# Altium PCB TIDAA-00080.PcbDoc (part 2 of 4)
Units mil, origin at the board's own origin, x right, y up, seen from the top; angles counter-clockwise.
Board outline 7874.02 x 2559.06 mil, 4 copper layers (Top Layer, MidLayer1, MidLayer2, Bottom Layer), stack 61.2 mil thick; 363 components, 169 nets, 940 pads, 199 vias.
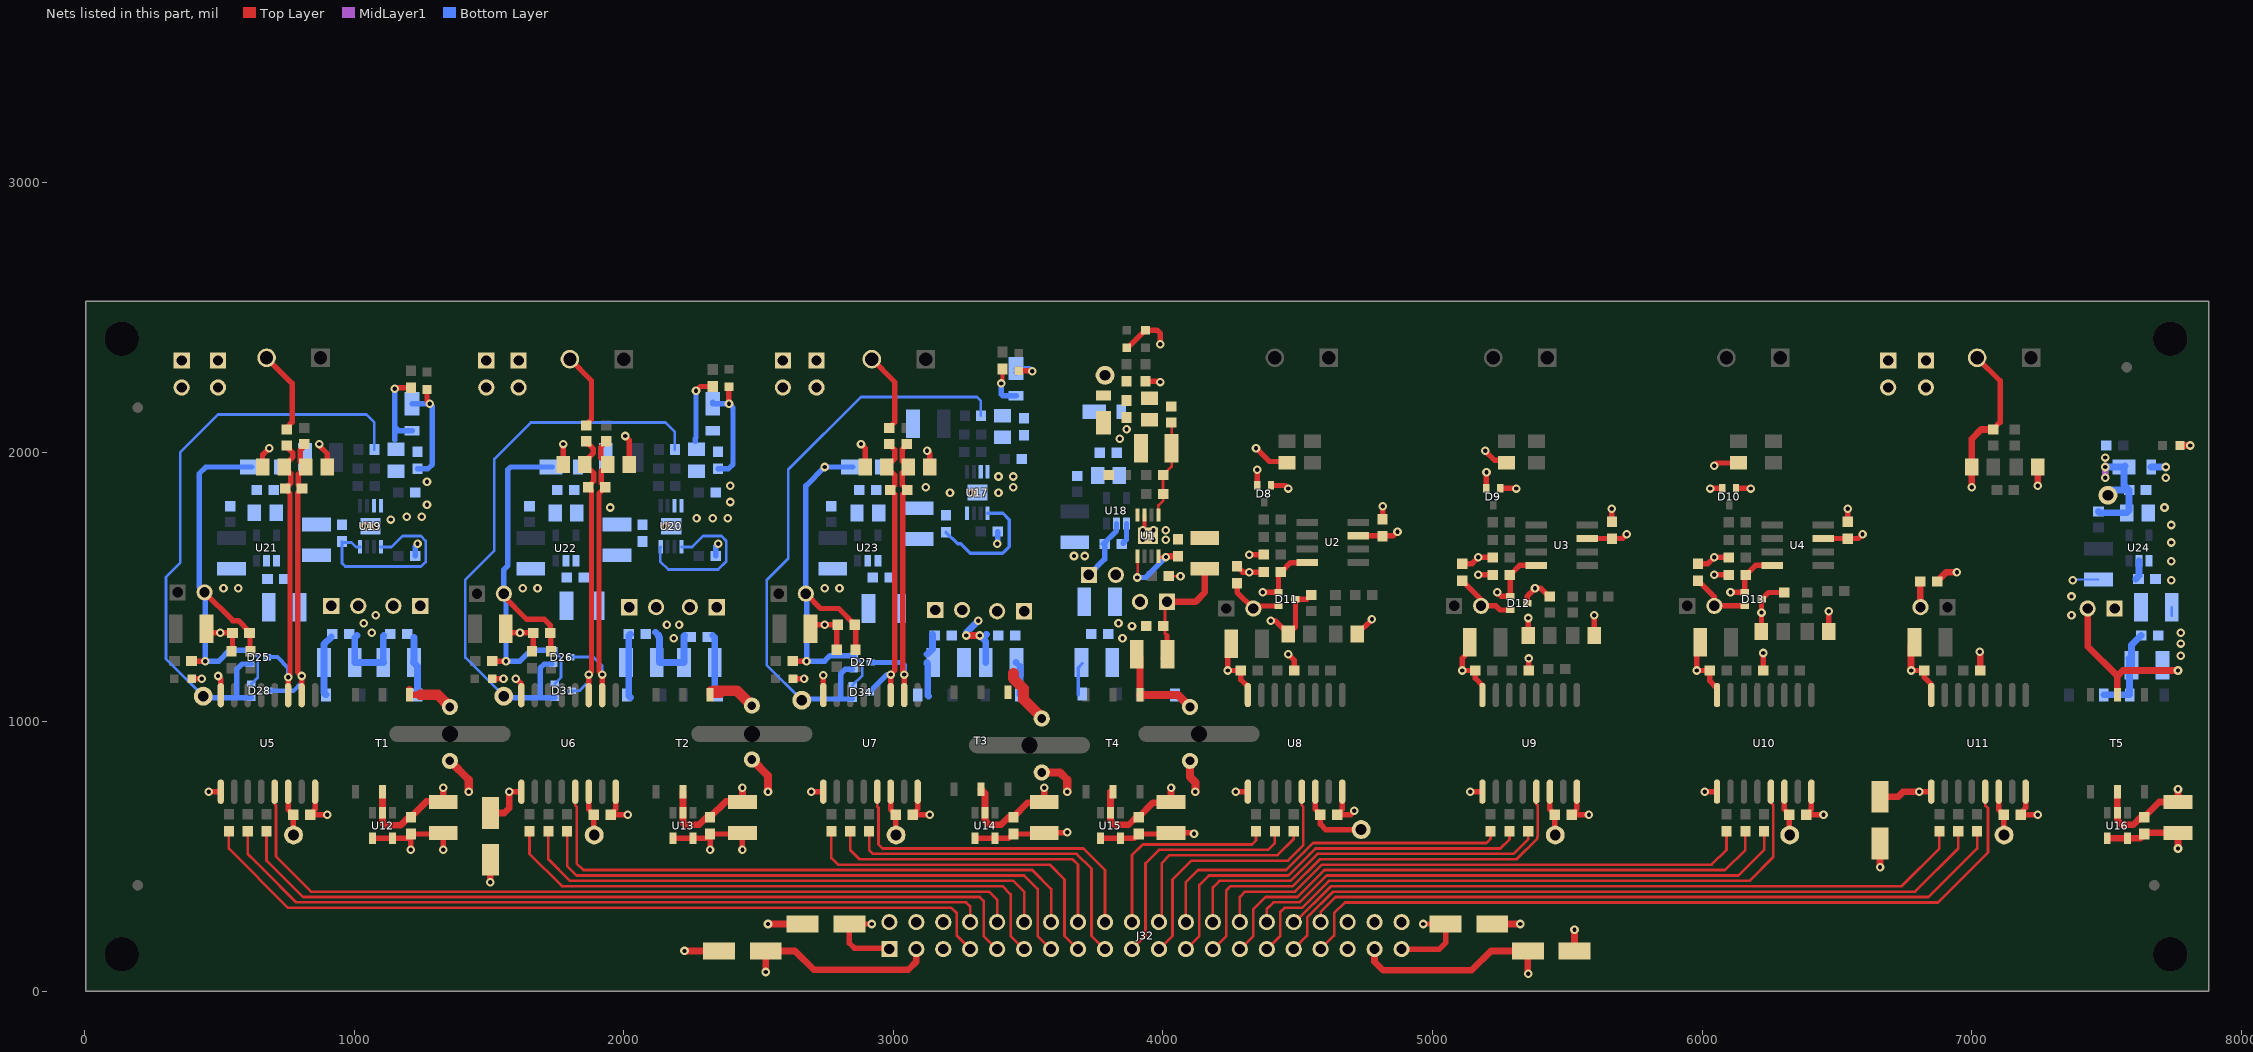
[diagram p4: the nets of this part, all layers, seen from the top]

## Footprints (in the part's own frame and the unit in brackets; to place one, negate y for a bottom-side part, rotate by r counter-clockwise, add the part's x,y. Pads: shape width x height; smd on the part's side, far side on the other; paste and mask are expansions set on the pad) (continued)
TI_Stacked_SolderMask_Small [mil]
  rect 0x0 smd paste-125 mask-125: 0(0,0)
  Top Layer region: 519 vertices and 0 holes, not listed, extent -418.39,-77.79 -237.37,98.14
  Top Layer region: 537 vertices and 1 holes, not listed, extent -104.32,-10.18 14.18,47.26
  Top Layer region: 271 vertices and 0 holes, not listed, extent 124.68,-98.14 197.38,-39.98
  Top Layer region: 193 vertices and 1 holes, not listed, extent 3.27,-98.14 65.79,-39.98
  Top Layer region: 243 vertices and 0 holes, not listed, extent -158.85,-98.14 -100.69,-39.98
  Top Layer region: 249 vertices and 0 holes, not listed, extent 255.54,-98.14 313.7,-39.98
  Top Layer region: -145.76,62.52 -145.04,62.52 -145.04,60.34 -144.31,60.34 -144.31,58.16 -143.58,58.16 -143.58,55.98 -142.86,55.98 -142.86,53.8 -142.13,53.8 -142.13,51.62 -141.4,51.62 -141.4,50.89 -142.13,50.89 -142.13,50.16 -143.58,50.16 -143.58,51.62 -144.31,51.62 -144.31,52.34 -145.04,52.34 -145.04,53.07 -145.76,53.07 -145.76,53.8 -147.22,53.8 -147.22,54.53 -147.94,54.53 -147.94,55.25 -150.13,55.25 -150.13,55.98 -153.03,55.98 -153.03,56.71 -168.3,56.71 -168.3,55.98 -169.03,55.98 -169.03,54.53 -169.75,54.53 -169.75,-2.91 -169.03,-2.91 -169.03,-5.09 -168.3,-5.09 -168.3,-5.82 -167.57,-5.82 -167.57,-6.54 -166.85,-6.54 -166.85,-7.27 -165.39,-7.27 -165.39,-8 -163.94,-8 -163.94,-10.18 -188.66,-10.18 -188.66,-8 -187.2,-8 -187.2,-7.27 -185.75,-7.27 -185.75,-6.54 -185.02,-6.54 -185.02,-5.82 -184.29,-5.82 -184.29,-5.09 -183.57,-5.09 -183.57,-2.18 -182.84,-2.18 -182.84,53.8 -183.57,53.8 -183.57,55.98 -185.02,55.98 -185.02,56.71 -199.56,56.71 -199.56,55.98 -202.47,55.98 -202.47,55.25 -204.65,55.25 -204.65,54.53 -205.38,54.53 -205.38,53.8 -206.83,53.8 -206.83,53.07 -207.56,53.07 -207.56,52.34 -208.29,52.34 -208.29,51.62 -209.01,51.62 -209.01,50.89 -209.74,50.89 -209.74,50.16 -210.47,50.16 -210.47,50.89 -211.19,50.89 -211.19,53.07 -210.47,53.07 -210.47,54.53 -209.74,54.53 -209.74,56.71 -209.01,56.71 -209.01,58.89 -208.29,58.89 -208.29,61.07 -207.56,61.07 -207.56,63.25 -206.83,63.25 -206.83,64.7 -145.76,64.7
  Top Layer region: 246.82,-41.44 247.54,-41.44 247.54,-42.89 248.27,-42.89 248.27,-45.07 249,-45.07 249,-47.26 249.72,-47.26 249.72,-48.71 250.45,-48.71 250.45,-50.89 251.18,-50.89 251.18,-53.07 250.45,-53.07 250.45,-53.8 249.72,-53.8 249.72,-53.07 249,-53.07 249,-52.34 248.27,-52.34 248.27,-51.62 246.82,-51.62 246.82,-50.89 246.09,-50.89 246.09,-50.16 245.36,-50.16 245.36,-49.44 244.64,-49.44 244.64,-48.71 243.18,-48.71 243.18,-47.98 241,-47.98 241,-47.26 238.09,-47.26 238.09,-46.53 222.83,-46.53 222.83,-47.26 220.64,-47.26 220.64,-48.71 219.92,-48.71 219.92,-63.98 237.37,-63.98 237.37,-63.25 239.55,-63.25 239.55,-62.52 240.27,-62.52 240.27,-61.8 241,-61.8 241,-60.34 241.73,-60.34 241.73,-58.89 243.91,-58.89 243.91,-74.88 241.73,-74.88 241.73,-73.43 241,-73.43 241,-71.97 240.27,-71.97 240.27,-71.25 238.09,-71.25 238.09,-70.52 219.92,-70.52 219.92,-88.69 220.64,-88.69 220.64,-90.15 241.73,-90.15 241.73,-89.42 244.64,-89.42 244.64,-88.69 246.09,-88.69 246.09,-87.97 247.54,-87.97 247.54,-87.24 248.27,-87.24 248.27,-86.51 249,-86.51 249,-85.79 249.72,-85.79 249.72,-85.06 250.45,-85.06 250.45,-84.33 251.18,-84.33 251.18,-83.61 251.91,-83.61 251.91,-82.88 253.36,-82.88 253.36,-83.61 254.09,-83.61 254.09,-85.06 253.36,-85.06 253.36,-86.51 252.63,-86.51 252.63,-88.69 251.91,-88.69 251.91,-90.15 251.18,-90.15 251.18,-92.33 250.45,-92.33 250.45,-93.78 249.72,-93.78 249.72,-95.96 249,-95.96 249,-97.42 201.74,-97.42 201.74,-95.24 203.2,-95.24 203.2,-94.51 204.65,-94.51 204.65,-93.78 206.1,-93.78 206.1,-93.06 206.83,-93.06 206.83,-90.88 207.56,-90.88 207.56,-45.8 206.83,-45.8 206.83,-44.35 206.1,-44.35 206.1,-43.62 205.38,-43.62 205.38,-42.89 203.92,-42.89 203.92,-42.17 201.74,-42.17 201.74,-39.98 246.82,-39.98
  Top Layer region: -110.14,45.8 -109.41,45.8 -109.41,44.35 -108.69,44.35 -108.69,42.17 -107.96,42.17 -107.96,39.98 -107.23,39.98 -107.23,37.8 -106.51,37.8 -106.51,36.35 -105.78,36.35 -105.78,33.44 -107.96,33.44 -107.96,34.17 -108.69,34.17 -108.69,34.9 -109.41,34.9 -109.41,35.62 -110.14,35.62 -110.14,36.35 -110.87,36.35 -110.87,37.08 -111.59,37.08 -111.59,37.8 -113.05,37.8 -113.05,38.53 -114.5,38.53 -114.5,39.26 -116.68,39.26 -116.68,39.98 -135.59,39.98 -135.59,39.26 -136.31,39.26 -136.31,38.53 -137.04,38.53 -137.04,23.26 -118.14,23.26 -118.14,23.99 -116.68,23.99 -116.68,24.72 -115.96,24.72 -115.96,26.17 -115.23,26.17 -115.23,27.63 -113.05,27.63 -113.05,11.63 -115.23,11.63 -115.23,13.81 -115.96,13.81 -115.96,14.54 -116.68,14.54 -116.68,15.27 -117.41,15.27 -117.41,15.99 -119.59,15.99 -119.59,16.72 -137.04,16.72 -137.04,-1.45 -136.31,-1.45 -136.31,-2.91 -134.13,-2.91 -134.13,-3.63 -118.86,-3.63 -118.86,-2.91 -113.78,-2.91 -113.78,-2.18 -111.59,-2.18 -111.59,-1.45 -110.14,-1.45 -110.14,-0.73 -109.41,-0.73 -109.41,0 -107.96,0 -107.96,0.73 -107.23,0.73 -107.23,1.45 -106.51,1.45 -106.51,2.18 -105.78,2.18 -105.78,2.91 -105.05,2.91 -105.05,3.63 -104.32,3.63 -104.32,4.36 -103.6,4.36 -103.6,3.63 -102.87,3.63 -102.87,2.18 -103.6,2.18 -103.6,0 -104.32,0 -104.32,-1.45 -105.05,-1.45 -105.05,-3.63 -105.78,-3.63 -105.78,-5.09 -106.51,-5.09 -106.51,-7.27 -107.23,-7.27 -107.23,-8.72 -107.96,-8.72 -107.96,-10.18 -155.21,-10.18 -155.21,-8 -153.03,-8 -153.03,-7.27 -151.58,-7.27 -151.58,-6.54 -150.85,-6.54 -150.85,-5.82 -150.13,-5.82 -150.13,-4.36 -149.4,-4.36 -149.4,41.44 -150.13,41.44 -150.13,42.89 -150.85,42.89 -150.85,43.62 -151.58,43.62 -151.58,44.35 -153.76,44.35 -153.76,45.07 -155.21,45.07 -155.21,47.26 -110.14,47.26
  Top Layer region: 293 vertices and 0 holes, not listed, extent 12,-10.9 59.25,47.98
  Top Layer region: 295 vertices and 0 holes, not listed, extent -98.51,-98.14 -51.25,-39.26
  Top Layer region: 283 vertices and 0 holes, not listed, extent 371.13,-98.14 418.39,-39.26
  Top Layer region: 121.05,-42.17 118.86,-42.17 118.86,-42.89 118.14,-42.89 118.14,-43.62 117.41,-43.62 117.41,-44.35 116.68,-44.35 116.68,-45.8 115.96,-45.8 115.96,-82.15 115.23,-82.15 115.23,-85.79 114.5,-85.79 114.5,-87.24 113.78,-87.24 113.78,-88.69 113.05,-88.69 113.05,-90.15 112.32,-90.15 112.32,-90.88 111.59,-90.88 111.59,-92.33 110.87,-92.33 110.87,-93.06 110.14,-93.06 110.14,-93.78 108.69,-93.78 108.69,-94.51 107.96,-94.51 107.96,-95.24 106.51,-95.24 106.51,-95.96 104.32,-95.96 104.32,-96.69 102.14,-96.69 102.14,-97.42 97.78,-97.42 97.78,-98.14 86.15,-98.14 86.15,-97.42 81.79,-97.42 81.79,-96.69 79.61,-96.69 79.61,-95.96 77.43,-95.96 77.43,-95.24 75.97,-95.24 75.97,-94.51 74.52,-94.51 74.52,-93.78 73.79,-93.78 73.79,-93.06 72.34,-93.06 72.34,-92.33 71.61,-92.33 71.61,-91.6 70.88,-91.6 70.88,-90.88 70.16,-90.88 70.16,-90.15 69.43,-90.15 69.43,-88.69 68.7,-88.69 68.7,-87.97 67.97,-87.97 67.97,-86.51 67.25,-86.51 67.25,-84.33 66.52,-84.33 66.52,-47.26 65.79,-47.26 65.79,-45.07 65.07,-45.07 65.07,-43.62 64.34,-43.62 64.34,-42.89 62.89,-42.89 62.89,-42.17 60.7,-42.17 60.7,-39.98 83.97,-39.98 83.97,-42.17 81.79,-42.17 81.79,-42.89 80.33,-42.89 80.33,-43.62 79.61,-43.62 79.61,-45.07 78.88,-45.07 78.88,-47.98 78.15,-47.98 78.15,-79.24 78.88,-79.24 78.88,-82.88 79.61,-82.88 79.61,-85.06 80.33,-85.06 80.33,-86.51 81.06,-86.51 81.06,-87.24 81.79,-87.24 81.79,-87.97 82.51,-87.97 82.51,-88.69 83.97,-88.69 83.97,-89.42 85.42,-89.42 85.42,-90.15 88.33,-90.15 88.33,-90.88 98.51,-90.88 98.51,-90.15 101.42,-90.15 101.42,-89.42 102.87,-89.42 102.87,-88.69 103.6,-88.69 103.6,-87.97 104.32,-87.97 104.32,-87.24 105.05,-87.24 105.05,-86.51 105.78,-86.51 105.78,-85.79 106.51,-85.79 106.51,-83.61 107.23,-83.61 107.23,-80.7 107.96,-80.7 107.96,-47.26 107.23,-47.26 107.23,-45.07 106.51,-45.07 106.51,-43.62 105.78,-43.62 105.78,-42.89 104.32,-42.89 104.32,-42.17 102.14,-42.17 102.14,-39.98 121.05,-39.98
  Top Layer region: -289.71,63.25 -290.44,63.25 -290.44,59.61 -291.16,59.61 -291.16,55.98 -291.89,55.98 -291.89,52.34 -292.62,52.34 -292.62,48.71 -293.34,48.71 -293.34,45.07 -294.07,45.07 -294.07,41.44 -294.8,41.44 -294.8,37.8 -295.53,37.8 -295.53,34.17 -296.25,34.17 -296.25,30.53 -296.98,30.53 -296.98,26.9 -297.71,26.9 -297.71,23.26 -298.43,23.26 -298.43,19.63 -299.16,19.63 -299.16,15.99 -299.89,15.99 -299.89,12.36 -300.61,12.36 -300.61,8.72 -301.34,8.72 -301.34,5.09 -302.07,5.09 -302.07,1.45 -302.8,1.45 -302.8,-2.18 -303.52,-2.18 -303.52,-5.82 -304.25,-5.82 -304.25,-9.45 -321.7,-9.45 -321.7,-7.27 -320.97,-7.27 -320.97,-3.63 -320.24,-3.63 -320.24,0 -319.52,0 -319.52,3.63 -318.79,3.63 -318.79,7.27 -318.06,7.27 -318.06,10.9 -317.34,10.9 -317.34,14.54 -316.61,14.54 -316.61,18.17 -315.88,18.17 -315.88,21.81 -315.15,21.81 -315.15,25.44 -314.43,25.44 -314.43,29.08 -313.7,29.08 -313.7,32.71 -312.97,32.71 -312.97,36.35 -312.25,36.35 -312.25,39.98 -311.52,39.98 -311.52,43.62 -310.79,43.62 -310.79,47.26 -310.07,47.26 -310.07,50.89 -309.34,50.89 -309.34,54.53 -308.61,54.53 -308.61,58.16 -307.88,58.16 -307.88,61.8 -307.16,61.8 -307.16,64.7 -289.71,64.7
  Top Layer region: -1.82,-42.17 -1.09,-42.17 -1.09,-45.07 -0.36,-45.07 -0.36,-47.26 0.36,-47.26 0.36,-49.44 1.09,-49.44 1.09,-51.62 1.82,-51.62 1.82,-55.25 0.36,-55.25 0.36,-54.53 -0.36,-54.53 -0.36,-53.8 -1.09,-53.8 -1.09,-53.07 -1.82,-53.07 -1.82,-52.34 -2.54,-52.34 -2.54,-51.62 -3.27,-51.62 -3.27,-50.89 -4,-50.89 -4,-50.16 -4.73,-50.16 -4.73,-49.44 -5.45,-49.44 -5.45,-48.71 -6.18,-48.71 -6.18,-47.98 -8.36,-47.98 -8.36,-47.26 -11.27,-47.26 -11.27,-46.53 -17.81,-46.53 -17.81,-47.26 -18.54,-47.26 -18.54,-47.98 -19.27,-47.98 -19.27,-90.88 -18.54,-90.88 -18.54,-93.06 -17.81,-93.06 -17.81,-93.78 -16.36,-93.78 -16.36,-94.51 -14.18,-94.51 -14.18,-95.24 -12.72,-95.24 -12.72,-97.42 -37.44,-97.42 -37.44,-95.24 -36.71,-95.24 -36.71,-94.51 -34.53,-94.51 -34.53,-93.78 -33.08,-93.78 -33.08,-93.06 -32.35,-93.06 -32.35,-91.6 -31.62,-91.6 -31.62,-47.26 -33.08,-47.26 -33.08,-46.53 -39.62,-46.53 -39.62,-47.26 -42.53,-47.26 -42.53,-47.98 -43.98,-47.98 -43.98,-48.71 -44.71,-48.71 -44.71,-49.44 -46.16,-49.44 -46.16,-50.16 -46.89,-50.16 -46.89,-50.89 -47.62,-50.89 -47.62,-52.34 -48.35,-52.34 -48.35,-53.07 -49.07,-53.07 -49.07,-53.8 -49.8,-53.8 -49.8,-54.53 -50.53,-54.53 -50.53,-55.25 -51.98,-55.25 -51.98,-54.53 -52.71,-54.53 -52.71,-53.8 -51.98,-53.8 -51.98,-51.62 -51.25,-51.62 -51.25,-49.44 -50.53,-49.44 -50.53,-47.26 -49.8,-47.26 -49.8,-44.35 -49.07,-44.35 -49.07,-42.17 -48.35,-42.17 -48.35,-39.98 -1.82,-39.98
  Top Layer region: -163.21,-23.99 -163.94,-23.99 -163.94,-24.72 -166.12,-24.72 -166.12,-25.44 -167.57,-25.44 -167.57,-26.17 -168.3,-26.17 -168.3,-26.9 -169.03,-26.9 -169.03,-29.08 -169.75,-29.08 -169.75,-90.15 -169.03,-90.15 -169.03,-92.33 -168.3,-92.33 -168.3,-93.06 -167.57,-93.06 -167.57,-93.78 -166.12,-93.78 -166.12,-94.51 -163.94,-94.51 -163.94,-95.24 -163.21,-95.24 -163.21,-97.42 -189.38,-97.42 -189.38,-95.24 -188.66,-95.24 -188.66,-94.51 -186.48,-94.51 -186.48,-93.78 -185.02,-93.78 -185.02,-93.06 -184.29,-93.06 -184.29,-91.6 -183.57,-91.6 -183.57,-89.42 -182.84,-89.42 -182.84,-29.81 -183.57,-29.81 -183.57,-27.63 -184.29,-27.63 -184.29,-26.17 -185.75,-26.17 -185.75,-25.44 -186.48,-25.44 -186.48,-24.72 -188.66,-24.72 -188.66,-23.99 -189.38,-23.99 -189.38,-22.54 -163.21,-22.54
  Top Layer region: 364.59,-40.71 365.32,-40.71 365.32,-42.89 366.04,-42.89 366.04,-45.07 366.77,-45.07 366.77,-47.26 367.5,-47.26 367.5,-50.16 368.23,-50.16 368.23,-52.34 368.95,-52.34 368.95,-55.25 366.77,-55.25 366.77,-53.8 366.04,-53.8 366.04,-53.07 365.32,-53.07 365.32,-52.34 364.59,-52.34 364.59,-51.62 363.86,-51.62 363.86,-50.89 363.14,-50.89 363.14,-50.16 362.41,-50.16 362.41,-49.44 361.68,-49.44 361.68,-48.71 360.96,-48.71 360.96,-47.98 358.77,-47.98 358.77,-47.26 355.87,-47.26 355.87,-46.53 349.32,-46.53 349.32,-47.26 348.6,-47.26 348.6,-47.98 347.87,-47.98 347.87,-91.6 348.6,-91.6 348.6,-93.06 349.32,-93.06 349.32,-93.78 350.78,-93.78 350.78,-94.51 352.96,-94.51 352.96,-95.24 353.69,-95.24 353.69,-97.42 329.69,-97.42 329.69,-95.24 330.42,-95.24 330.42,-94.51 332.6,-94.51 332.6,-93.78 334.06,-93.78 334.06,-93.06 334.78,-93.06 334.78,-91.6 335.51,-91.6 335.51,-47.98 334.78,-47.98 334.78,-47.26 334.06,-47.26 334.06,-46.53 327.51,-46.53 327.51,-47.26 324.61,-47.26 324.61,-47.98 323.15,-47.98 323.15,-48.71 321.7,-48.71 321.7,-49.44 320.97,-49.44 320.97,-50.16 320.24,-50.16 320.24,-50.89 319.52,-50.89 319.52,-51.62 318.79,-51.62 318.79,-53.07 318.06,-53.07 318.06,-53.8 317.34,-53.8 317.34,-54.53 316.61,-54.53 316.61,-55.25 315.15,-55.25 315.15,-54.53 314.43,-54.53 314.43,-53.8 315.15,-53.8 315.15,-51.62 315.88,-51.62 315.88,-48.71 316.61,-48.71 316.61,-46.53 317.34,-46.53 317.34,-44.35 318.06,-44.35 318.06,-42.17 318.79,-42.17 318.79,-39.98 364.59,-39.98
  Top Layer region: -285.35,85.79 -286.07,85.79 -286.07,82.15 -286.8,82.15 -286.8,78.52 -287.53,78.52 -287.53,74.88 -288.26,74.88 -288.26,71.97 -305.7,71.97 -305.7,73.43 -304.98,73.43 -304.98,77.06 -304.25,77.06 -304.25,80.7 -303.52,80.7 -303.52,84.33 -302.8,84.33 -302.8,87.97 -302.07,87.97 -302.07,88.69 -285.35,88.69
TP-040_RND [mil]
  round 70 / inner round 62 / far side round 62 hole 40: 1(0,0)
  silkscreen extent -45,-45 45,45

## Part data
C1 C85 C90 C92 C95 C102 C103 C104 C106: library part C2012X5R1H475K125AB, "CAP, CERM, 4.7uF, 50V, +/-10%, X5R, 0805"
C2 C20 C22 C24 C26 C29 C30 C31 C32 C33 C34 C35 C36 C39 C42 C45 C46 C47 C48 C50 C52 C54 C56 C69 C71 C73 C75 C77 C86 C87 C89 C93 C96 C98 C100 C101 C105 C112 C114 C115 C118 C119 C122 C124 C127 C128 C130 C132 C133 C134 C135 C137: library part C0603C104K5RACTU, "CAP, CERM, 0.1uF, 50V, +/-10%, X7R, 0603"
C3 C4 C5 C6 C7 C8 C10 C11 C37 C38 C40 C41 C43 C44: "CAP, CERM, 47pF, 500V, +/-5%, C0G/NP0, 0805"
C9 C17 C18 C19 C28 C49 C70 C72 C74 C76 C78 C84 C88 C91 C107 C108 C109 C111 C113 C117 C121 C123 C125 C126 C129 C131 C136 C138 C139 C140 C141 C142 C143 C144 C145 C146 C147 C148 C149: library part GMK325AB7106MM-T, "CAP, CERM, 10uF, 35V, +/-20%, X7R, 1210"
C12 C13 C14 C16 C51 C53 C55: "CAP, CERM, 1500pF, 100V, +/-10%, X7R, 0603"
C15 C27 C94 C97 C99 C110 C116 C120: library part 06031C103JAT2A, "CAP, CERM, 0.01uF, 100V, +/-5%, X7R, 0603"
C21 C23 C25: library part 06031C472KAT2A, "CAP, CERM, 4700pF, 100V, +/-10%, X7R, 0603"
C57 C58 C59 C60: library part 202R18W102KV4E, "CAP CER 1000PF 1KV 10% RADIAL"
C61 C62 C63 C64 C65 C66 C67: library part 06033C104JAT2A, "CAP, CERM, 0.1uF, 25V, +/-5%, X7R, 0603"
C68 C79 C80 C81 C82 C83: "CAP, AL, 22uF, 25V, +/-20%, 0.76 ohm, SMD"
D1 D2 D3 D4 D5 D7 D14 D15 D16: library part "LED_LG L29K-G2J1-24-Z", "LED SmartLED Green 570NM"
D6 D17 D18 D19 D20 D21 D22 D23 D24: library part DFLZ6V2-7, "Diode, Zener, 6.2V, 1W, PowerDI123"
D8 D9 D10 D11 D12 D13 D25 D26 D27 D28 D31 D34: library part BAV99WT1G, "Diode, P-N, 70V, 0.2A, SOT-323"
D29 D30 D32 D33 D35 D36 D37 D38 D39 D40: library part MBR0520LT1G, "Diode, Schottky, 20V, 0.5A, SOD-123"
FB1 FB8 FB9 FB10 FB11 FB12 FB13 FB14 FB15: library part MMZ1608B102C, "FERRITE CHIP 1000 OHM 300MA 0603"
FB2 FB3 FB4 FB5 FB6 FB7 FB16 FB17 FB18 FB19 FB20 FB21 FB22 FB23: "FERRITE CHIP 1000 OHM 300MA 0603"
FID1 FID2 FID3 FID4 FID5 FID6 FID7 FID8: library part Fiducial, "Fiducial mark.  There is nothing to buy or mount."
J1 J2 J3 J4 J5 J6 J7 J8 J16 J17 J18 J19 J20 J21 J22 J23 J24 J25 J26 J27 J28 J29 J30 J31: library part JUMPER_2X100MIL, "Header, Male 2-pin, 100mil spacing,"
J9 J10 J11 J12 J13 J14 J15: "TERMINAL BLOCK 5.08MM VERT 2POS, TH"
J32: library part CONN_61304021021, "Connector, Right Angle 2x20 pin, 100mil spacing"
LBL1: library part THT-14-423-10, "Thermal Transfer Printable Labels, 0.650\" W x 0.200\" H - 10,000 per roll"
Logo1: library part TI_Logo, "Texas Instrument Corporate Signature"
MH1 MH2 MH3 MH4: library part "NY PMS 440 0025 PH", "Mountin hole, NPTH Drill 3.2mm"
R1 R2 R3 R4 R5 R28 R30 R32 R60: library part CRCW06033K90JNEA, "RES, 3.9k ohm, 5%, 0.1W, 0603"
R6 R9 R12: "RES, 0 ohm, 5%, 0.1W, 0603"
R7 R8 R10 R11 R13 R19: "RES, 0 ohm, 5%, 0.125W, 0805"
R14 R63 R64 R65: library part CRCW060311K5FKEA, "RES, 11.5k ohm, 1%, 0.1W, 0603"
R15 R59 R61 R62: library part RT0603BRD0737KL, "RES 37.4K OHM 1/10W .1% 0603 SMD"
R16 R17 R18: library part RC0603FR-074K7L, "RES, 4.70k ohm, 1%, 0.1W, 0603"
R21 R24 R27 R29 R31 R33 R34 R35 R36 R37 R40 R43 R45 R49 R52 R54 R57: library part CRCW06030000Z0EA, "RES, 0 ohm, 5%, 0.1W, 0603"
R38 R39 R41 R42 R44 R46 R47 R48 R50 R51 R53 R55 R56 R58: library part CRCW060310R0FKEA, "RES, 10.0 ohm, 1%, 0.1W, 0603"
T1 T2 T3 T4 T5: library part TRNSFMR, "Transformer 469uH SMD"
TP1 TP2 TP3 TP4 TP5 TP6 TP7 TP8 TP9 TP10 TP11 TP12: library part TP-040_RND, "Test Point, O.040 Hole"
U1 U17 U20: library part TPS7A3001DGNR, "-36V, -200mA, Ultralow-Noise, Negative Linear Regulator"
U2 U3 U4: library part OPA211AID, "IC, 1.1nV/vHz Noise, Low Power, Precision OpAmp"
U5 U6 U7 U8 U9 U10 U11: library part AMC1304L25, "20 MHz, Isolated Delta-Sigma Modulator, LVDS interface:"
U12 U13 U14 U15 U16: "Transformer Driver for Isolated Power Supplies, DBV0005A"
U18 U21 U22 U23 U24: "Regulator, LDO, 5V, 0.15A, SOT23-5"
U19: "-36V, -200mA, Ultralow-Noise, Negative Linear Regulator"
ZZ1: library part AssemblyNoteLabel, "This Assembly Note is for PCB labels only"
ZZ2: library part AssemblyNote, "These assemblies are ESD sensitive, ESD precautions shall be observed."
ZZ3: library part AssemblyNote, "These assemblies must be clean and free from flux and all contaminants. Use of no clean flux is not acceptable."
ZZ4: library part AssemblyNote, "These assemblies must comply with workmanship standards IPC-A-610 Class 2, unless otherwise specified."

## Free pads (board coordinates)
  oval 450x60 hole 60 slot 450 at 0 deg unplated mask+10: 0(1355,955) 0(2475,955) 0(3505,913) 0(4133.86,955)

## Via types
v1: diameter 32, hole 16, Top Layer to Bottom Layer, tented both sides, 199 vias

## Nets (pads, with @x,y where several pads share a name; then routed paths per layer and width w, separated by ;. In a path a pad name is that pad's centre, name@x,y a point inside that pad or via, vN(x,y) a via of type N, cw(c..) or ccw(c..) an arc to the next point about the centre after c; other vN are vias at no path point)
+3.3V_DVDD: C61.2 C62.2 C63.2 C64.2 C65.2 C66.2 C67.2 C80.1 C81.1 J32.1 J32.39 TP6.1 TP7.1 TP8.1 TP9.1 TP10.1 TP11.1 TP12.1 U5.14 U6.14 U7.14 U8.14 U9.14 U10.14 U11.14 | length 1942.7
  Top Layer w20: U5.14@755,740.55 755,675 C61.2@775,655 ; C61.2@773.5,655 773.5,586.5 TP6.1@780,580 ; U6.14@1870,740.55 1870,675 C62.2@1890,655 ; C62.2@1888.5,655 1888.5,586.5 TP7.1@1890,585 ; v1(2920,250) C80.1@2836.61,250 2836.61,178.39 2855,160 2981.7,160 J32.1@2985.01,156.69 ; U7.14@2990,740.87 2990,675 C66.2@3010,655 ; C66.2@3008.5,655 3008.5,581.5 TP8.1@3010,580 ; U8.14@4565,740.87 4565,675 C67.2@4585,655 ; C67.2@4583.5,655 4583.5,620 4603.5,600 TP9.1@4735,600 ; J32.39@4885.01,156.69 5025,156.69 5048.39,180.08 C81.1@5048.39,250 v1(4965,250) ; U9.14@5435,740.87 5435,675 C63.2@5455,655 ; C63.2@5453.5,655 5453.5,581.5 TP10.1@5455,580 ; U10.14@6305,740.87 6305,675 C64.2@6325,655 ; C64.2@6323.5,655 6323.5,581.5 TP11.1@6325,580 ; U11.14@7100,740.87 7100,675 C65.2@7120,655 ; C65.2@7118.5,655 7118.5,581.5 TP12.1@7120,580
+5.0V_PH: C22.2 C24.2 C26.2 C36.1 C39.1 C42.1 C87.1 C95.2 D8.2 D9.2 D10.2 D11.2 D12.2 D13.2 D18.1 FB11.2 J28.2 J29.2 J30.2 R2.2 R34.1 R35.1 R36.1 U2.7 U3.7 U4.7 | length 1544
  Top Layer w20: R2.2@3935,2263.5 3988.5,2263.5 3990,2265 v1(3990,2260) ; C36.1@4275,1513.5 4275,1480 J28.2@4335,1420 4344.41,1429.41 D11.2@4428.5,1429.41 ; D8.2@4349.41,1876.5 4349.41,1934.41 v1(4350,1935) ; v1(4465,1250) 4486.5,1228.5 R34.1@4486.5,1190 ; U2.7@4724,1690 4855,1690 v1(4870,1705) ; C39.1@5110,1523.5 5180,1453.5 J29.2@5180,1430 5235,1430 5250.59,1414.41 D12.2@5288.5,1414.41 ; D9.2@5199.41,1866.5 5199.41,1924.41 v1(5200,1925) ; R35.1@5356.5,1190 v1(5356.5,1235) ; U3.7@5574,1680 5705,1680 v1(5720,1695) ; C42.1@5985,1523.5 6045,1463.5 J30.2@6045,1430 6157.91,1430 D13.2@6158.5,1429.41 ; v1(6030,1865) 6031.5,1866.5 D10.2@6074.41,1866.5 ; R36.1@6226.5,1190 v1(6226.5,1255) ; U4.7@6449,1680 6580,1680 v1(6595,1695)
+5.0V_USH: C32.1 C96.1 C102.2 D21.1 D25.2 D28.2 FB12.2 J26.2 R28.2 R29.1 | length 1580.1
  Top Layer w20: R28.2@396.5,1225 v1(447.89,1225) ; J26.2@445,1480 550,1375 570,1375 611.5,1333.5 C32.1@611.5,1330 C32.1@613.5,1330 ; C32.1@613.5,1320 613.5,1262.99 R29.1@615,1261.5
  Bottom Layer w10: D28.2@618.5,1140.59 642.25,1164.34 642.25,1239.43 618.5,1263.18 D25.2@618.5,1265.59
  Bottom Layer w20: D25.2@613.5,1265.59 538.24,1265.59 497.65,1225 v1(447.89,1225) 447.89,1477.11 J26.2@445,1480 425,1500 425,1920 450,1945 D21.1@619.81,1945 D21.1@620,1945
+5.0V_VDC: C45.1 C101.1 C106.2 D24.1 FB15.2 J31.2 R37.1 R60.2 TP2.1 | length 630.8
  Top Layer w25: C45.1@6808.5,1520 6808.5,1426.5 J31.2@6810,1425 ; R37.1@7031.5,1190 v1@7031.5,1258.5
  MidLayer1 w25: v1(7495,1905) v1(7495,1945)
  Bottom Layer w25: FB15.2@7470,1779.53 7474.53,1775 C106.2@7575,1775 7583.5,1783.5 C101.1@7583.5,1860 ; v1(7495,1945) D24.1@7564.8,1945 ; TP2.1@7520,1860 C101.1@7583.5,1860 ; D24.1@7568.5,1948.7 D24.1@7564.8,1945 ; D24.1@7564.8,1945 7564.8,1878.7 C101.1@7583.5,1860
  other v1: 7030,1260 7495,1980
+5.0V_VSH: C33.1 C98.1 C103.2 D22.1 D26.2 D31.2 FB13.2 J27.2 R30.2 R31.1 | length 1575.2
  Top Layer w20: R30.2@1511.5,1225 v1(1562.89,1225) ; J27.2@1555,1465 1640,1380 1705,1380 1726.5,1358.5 C33.1@1726.5,1330 ; C33.1@1728.5,1320 1728.5,1262.99 R31.1@1730,1261.5
  Bottom Layer w10: D26.2@1738.5,1265.59 1767.25,1236.84 1767.25,1164.34 D31.2@1743.5,1140.59
  Bottom Layer w20: J27.2@1555,1475 1555,1565 1570,1580 1570,1935 1580,1945 D22.1@1729.8,1945 D22.1@1734.81,1945 ; J27.2@1560,1470 1562.89,1467.11 v1(1562.89,1225) 1614.41,1225 1655,1265.59 D26.2@1738.5,1265.59
+5.0V_WSH: C34.1 C100.1 C104.2 D23.1 D27.2 D34.2 FB14.2 J22.2 R32.2 R33.1 | length 1548.3
  Top Layer w20: R32.2@2626.5,1225 v1(2677.89,1225) ; J22.2@2675,1475 2730,1420 2797.35,1420 2856.5,1360.85 C34.1@2856.5,1360 2860,1356.5 R33.1@2860,1266.5
  Bottom Layer w10: D34.2@2848.5,1135.59 2885,1172.09 2885,1214.09 D27.2@2853.5,1245.59
  Bottom Layer w20: v1(2745,1945) 2675,1875 J22.2@2675,1475 2677.89,1472.11 v1(2677.89,1225) 2745,1225 2765.59,1245.59 D27.2@2853.5,1245.59 ; v1@2750,1945 D23.1@2849.8,1945
+5V_CNTL: C68.1 C69.2 C70.2 C71.2 C72.2 C73.2 C74.2 C75.2 C76.2 C77.2 C78.2 C79.1 C82.1 C83.1 J32.3 J32.37 T1.2 T2.2 T3.2 T4.2 T5.2 U12.2 U13.2 U14.2 U15.2 U16.2 | length 3783.1
  Top Layer w25: T1.2@1105,740 U12.2@1105,662.24 1105,625 1113.44,616.56 1172.85,616.56 1201.29,645 C71.2@1205,645 ; C71.2@1210,646.5 1268.5,705 C72.2@1330,705 ; C72.2@1330,702.09 C72.2@1330,705 ; v1(1330,755) C72.2@1330,705 ; v1(1505,405) C79.1@1505,488.39 ; T2.2@2220,740 U13.2@2220,662.24 2220,625 2226.91,618.09 2279.52,618.09 2307.92,646.5 C73.2@2320,646.5 2378.5,705 C74.2@2440,705 ; C74.2@2440,702.09 C74.2@2440,705 ; v1(2440,755) C74.2@2440,705 ; v1(2526.61,71.61) C82.1@2526.61,150 2635,150 2705,80 3055,80 3085.01,110.01 J32.3@3085.01,156.69 ; T3.2@3325,750 3340,735 U14.2@3340,662.24 3340,633.38 3355.29,618.09 3399.52,618.09 3427.92,646.5 C75.2@3441.5,646.5 ; C75.2@3445,650 C75.2@3441.5,646.5 ; C76.2@3560,700 3498.5,700 C75.2@3445,646.5 C75.2@3441.5,646.5 ; C76.2@3560,702.09 v1(3560,755) ; T4.2@3805,740 U15.2@3805,662.24 3805,635 3807.11,632.89 3807.11,631.27 3820.29,618.09 3873.09,618.09 3901.5,646.5 C77.2@3910,646.5 3963.5,700 C78.2@4030,700 ; C78.2@4030,702.09 v1(4030,755) ; J32.37@4785.01,156.69 4785.01,109.99 4816.61,78.39 5145,78.39 5216.61,150 C83.1@5353.39,150 5353.39,66.61 v1(5355,65) ; v1(6660,460) C68.1@6660,548.39 ; T5.2@7540,740 U16.2@7540,662.24 7540,633.38 7555.29,618.09 7599.52,618.09 7627.92,646.5 C69.2@7640,646.5 7695.59,702.09 C70.2@7765,702.09 v1(7765,750)
  Bottom Layer w25: v1@2525,70 v1(2526.61,71.61)
+6V_PH: C112.1 C125.2 C134.1 C144.1 D37.1 J16.1 U18.2 | length 359.2
  Bottom Layer w12: 3685,1145 3685.53,1145 ; D37.1@3685.53,1100 3685.53,1145 ; C144.1@3701.46,1216.46 3685.53,1200.53 3685.53,1145 ; C112.1@3772.4,1659.25 C112.1@3780.91,1667.76
  Bottom Layer w20: J16.1@3725,1545 3783.5,1603.5 C112.1@3783.5,1660 ; C112.1@3787.4,1667.76 3814.21,1694.57 3814.21,1694.74 3827.4,1707.93 U18.2@3827.4,1735.51
+6V_USH: C114.1 C126.2 C127.1 C138.1 D29.1 J18.1 U21.2 | length 229.2
  Bottom Layer w25: D29.1@895,1100 887.91,1107.09 C138.1@887.91,1220 887.91,1287.91 C127.1@915,1315
+6V_VDC: C124.1 C135.1 C136.2 C145.1 D39.1 D40.1 J25.1 U24.2 | length 429.4
  Bottom Layer w25: D39.1@7489.47,1100 D40.1@7585.53,1100 7585.53,1232.38 C145.1@7582.91,1235 ; C145.1@7592.91,1210 7592.91,1284.41 C135.1@7628.5,1320 ; C124.1@7608.5,1530 7620,1541.5 U24.2@7620,1597.76
+6V_VSH: C118.1 C129.2 C137.1 C140.1 D32.1 J20.1 U22.2 | length 240.9
  Bottom Layer w25: D32.1@2025,1090 2017.91,1097.09 2017.91,1220 2017.91,1317.91 C137.1@2025,1325
+6V_WSH: C122.1 C131.2 C132.1 C142.1 D35.1 J23.1 U23.2 | length 209.1
  Bottom Layer w25: C142.1@3125,1215 C142.1@3125,1220 ; C142.1@3125,1250 3145,1270 3145,1320 C132.1@3145,1325 ; C142.1@3127.91,1215 3127.91,1097.09 3130,1095
-5.0V_PH: C1.2 C2.1 C29.2 C30.2 C31.2 D6.2 D8.1 D9.1 D10.1 D11.1 D12.1 D13.1 FB1.2 R1.2 TP1.1 U2.4 U3.4 U4.4 | length 914
  Top Layer w20: v1(4370,1480) 4370.59,1480.59 D11.1@4428.5,1480.59 4428.5,1545.34 C29.2@4437.33,1554.16 ; D8.1@4400.59,1876.5 4453.5,1876.5 v1(4465,1865) ; C29.2@4436.5,1555 C29.2@4437.33,1554.16 ; U2.4@4535,1590 4473.17,1590 C29.2@4437.33,1554.16 ; v1(5240,1480) 5254.41,1465.59 D12.1@5288.5,1465.59 5288.5,1542.99 C30.2@5286.5,1545 5288.17,1545 5323.17,1580 U3.4@5385,1580 ; D9.1@5250.59,1866.5 5308.5,1866.5 v1(5310,1865) ; v1(6105,1480) 6105.59,1480.59 D13.1@6158.5,1480.59 6158.5,1542.01 C31.2@6161.5,1545 6163.17,1545 6198.17,1580 U4.4@6260,1580 ; D10.1@6125.59,1866.5 6178.5,1866.5 v1(6180,1865)
-5.0V_USH: C89.1 C90.2 D19.2 D25.1 D28.1 FB9.2 R3.2 TP3.1 | length 2544.4
  Top Layer w20: v1(1150,2235) 1153.5,2238.5 R3.2@1210,2238.5
  Bottom Layer w10: TP3.1@440,1095 302,1233 302,1537 355,1590 355,2000 495,2140 1045,2140 1074.53,2110.47 FB9.2@1074.53,2010
  Bottom Layer w20: TP3.1@440,1095 445.59,1089.41 D28.1@618.5,1089.41 ; 565,1090 565,1195 584.41,1214.41 D25.1@613.5,1214.41 D25.1@618.5,1214.41 ; 1150,2045 1150,2095 ; v1(1150,2235) 1150,2095 ; D19.2@1215,2079.8 1165.2,2079.8 1150,2095
-5.0V_VSH: C92.2 C93.1 D20.2 D26.1 D31.1 FB10.2 R4.2 TP4.1 | length 2396.3
  Top Layer w20: v1(2268,2228) 2283.5,2243.5 R4.2@2330,2243.5
  Bottom Layer w10: TP4.1@1555,1095 1412,1238 1412,1527 1520,1635 1520,1975 1655,2110 2155,2110 2189.53,2075.47 FB10.2@2189.53,2010
  Bottom Layer w20: TP4.1@1555,1095 1560.59,1089.41 D31.1@1743.5,1089.41 ; 1690,1090 1690,1198.82 1705.59,1214.41 D26.1@1733.5,1214.41 ; 2265,2040.2 2265,2050 2268,2053 v1(2268,2228)
-5.0V_WSH: C85.2 C86.1 D17.2 D27.1 D34.1 FB8.2 R5.2 TP5.1 | length 2318.1
  Top Layer w15: v1@3401.5,2253.5 3405,2257.01 R5.2@3405,2308.5
  Bottom Layer w10: TP5.1@2664.41,1084.41 TP5.1@2660,1080 2530,1210 2530,1525 2610,1605 2610,1935 2880,2205 3310,2205 3324.53,2190.47 FB8.2@3324.53,2135
  Bottom Layer w20: TP5.1@2664.41,1084.41 2805,1084.41 ; D34.1@2848.5,1084.41 2805,1084.41 ; D27.1@2848.5,1194.41 2820.59,1194.41 2805,1178.82 2805,1084.41 ; v1(3400,2255) 3400,2215 3405.2,2209.8 D17.2@3455,2209.8
-6V_PH: C20.1 C28.2 C35.2 C49.2 D38.2 J17.1 U1.5 U1.8 | length 749.1
  Top Layer w10: v1(3905,1535) 3906.2,1536.2 U1.5@3906.2,1613.4
  Top Layer w12: U1.8@3983,1613.4 3986.4,1610 4010.9,1610 v1(4010.9,1610.9) ; 4015,1320 4007.09,1327.91 4007.09,1445 J17.1@4015,1445
  Top Layer w20: C49.2@4001.5,1235 4015,1248.5 4015,1320
  Top Layer w25: v1@4010.9,1610 4014.4,1613.5 C20.1@4055,1613.5 ; J17.1@4015,1445 4120,1445 4155,1480 C28.2@4155,1562.91
  Bottom Layer w12: 4025,1095 D38.2@4027.09,1097.09
  Bottom Layer w20: v1@3915,1535 3935,1535 v1(4010.9,1610.9)
-6V_USH: C107.2 C115.1 C128.2 C139.2 D30.2 J19.1 U19.5 U19.8 | length 963.8
  Bottom Layer w10: C115.1@955,1668.5 C115.1@955,1665 ; U19.8@1022,1648.4 1006.6,1648.4 990,1665 C115.1@955,1665 ; U19.5@1098.8,1648.4 1138.4,1648.4 1179,1689 1247.01,1689 1265,1671.01 1265,1593 1248,1576 967,1576 955,1588 C115.1@955,1665
  Bottom Layer w25: C139.2@1220,1220 1234.47,1205.53 D30.2@1234.47,1100 ; C139.2@1222.09,1220 1222.09,1312.91
-6V_VSH: C108.2 C119.1 C130.2 C141.2 D33.2 J21.1 U20.5 U20.8 | length 813.8
  Bottom Layer w10: U20.8@2137,1648.4 2135,1646.4 2135,1595 2165,1565 2350,1565 2380,1595 2380,1671.01 2362.01,1689 2294,1689 2253.4,1648.4 U20.5@2213.8,1648.4
  Bottom Layer w25: C130.2@2330,1320 2337.09,1312.91 C141.2@2337.09,1220 2337.09,1117.91 D33.2@2350,1105
-6V_WSH: C105.1 C109.2 C133.2 C143.2 D36.2 J24.1 U17.5 U17.8 | length 575
  Bottom Layer w12: C105.1@3195,1703.5 3238.5,1660 3250,1660 3285,1625 3405,1625 3430,1650 3430,1750 3406.6,1773.4 U17.5@3349.6,1773.4
  Bottom Layer w25: C143.2@3455,1220 C143.2@3456.04,1218.96 ; D36.2@3469.47,1100 C143.2@3469.47,1205.53
CLKN_CH_U: J32.9 R40.2 | length 3031.3
  Top Layer w10: R40.2@675,593.5 675,485 810,350 3320,350 3335,335 3335,205 J32.9@3385,155
CLKN_CH_V: J32.13 R43.2 | length 2155.9
  Top Layer w10: R43.2@1790,595 R43.2@1790,593.5 1790,465 1825,430 3485,430 3535,380 3535,205 J32.13@3585,155
CLKN_CH_W: J32.17 R45.2 | length 1243.2
  Top Layer w10: R45.2@2910,593.5 2910,525 2925,510 3680,510 3735,455 3735,205 J32.17@3785,155
CLKN_U_PH: J32.22 R49.2 | length 779.7
  Top Layer w10: J32.22@3985.01,256.69 3995,266.68 3995,475 4025,505 4425,505 4485,565 R49.2@4485,593.5 R49.2@4485,595
CLKN_V_PH: J32.26 R52.2 | length 1398.2
  Top Layer w10: J32.26@4185,260 4185,385 4210,410 4473.58,410 4573.28,509.7 4573.28,510 5300,510 5355,565 R52.2@5355,593.5
CLKN_VDC: J32.34 R57.2 | length 2625.6
  Top Layer w10: J32.34@4585.01,256.69 4585.01,295 4639.85,349.84 6839.84,349.84 7020,530 R57.2@7020,585
CLKN_W_PH: J32.30 R54.2 | length 2059.6
  Top Layer w10: J32.30@4385,250 4385,305 4410,330 4506.72,330 4606.72,430 6135,430 6230,525 R54.2@6230,593.5
CLKP_CH_U: J32.10 U5.13 | length 3078.3
  Top Layer w10: U5.13@705,750 U5.13@705,740.55 705,695 710,690 710,500 840,370 3355,370 3385,340 J32.10@3385,255
CLKP_CH_V: J32.14 U6.13 | length 2199.7
  Top Layer w10: U6.13@1820,750 U6.13@1820,740.55 1820,690 1825,685 1825,475 1850,450 3515,450 3585.01,379.99 J32.14@3585.01,256.69
CLKP_CH_W: J32.18 U7.13 | length 1272.3
  Top Layer w10: U7.13@2940,740.87 2940,686.1 2945,681.1 2945,545 2960,530 3705,530 3785,450 J32.18@3785,255
CLKP_U_PH: J32.21 U8.13 | length 1028.8
  Top Layer w10: J32.21@3985,155 4035,205 4035,415 4105,485 4463.73,485 4503.28,524.55 4503.28,524.85 4520,541.57 4520,685 4515,690 U8.13@4515,740.87 U8.13@4515,750
CLKP_V_PH: J32.25 U9.13 | length 1650.1
  Top Layer w10: J32.25@4185,155 4235,205 4235,375 4250,390 4481.86,390 4581.86,490 5311.1,490 5388.7,567.61 5388.7,573.7 5390,575 5390,690 5385,695 U9.13@5385,740.87
CLKP_VDC: J32.33 U11.13 | length 2902.2
  Top Layer w10: J32.33@4585.01,156.69 4635,206.68 4635,290 4674.84,329.84 6874.84,329.84 7060,515 7060,680 7050,690 U11.13@7050,740.87
CLKP_W_PH: J32.29 U10.13 | length 2318.7
  Top Layer w10: J32.29@4385,155 4435,205 4435,295 4450,310 4515,310 4615,410 6175,410 6263.7,498.7 6263.7,691.1 6255,699.8 U10.13@6255,740
DGND: C57.1 C58.1 C59.1 C60.1 C61.1 C62.1 C63.1 C64.1 C65.1 C66.1 C67.1 C68.2 C69.1 C70.1 C71.1 C72.1 C73.1 C74.1 C75.1 C76.1 C77.1 C78.1 C79.2 C80.2 C81.2 C82.2 C83.2 J32.2 J32.4 J32.5 J32.6 J32.35 J32.36 J32.38 J32.40 U5.9 U5.16 U6.9 U6.16 U7.9 U7.16 U8.9 U8.16 U9.9 U9.16 U10.9 U10.16 U11.9 U11.16 U12.4 U12.5 U13.4 U13.5 U14.4 U14.5 U15.4 U15.5 U16.4 U16.5 | length 4529.9
  Top Layer w20: v1(460,740) 460.55,740.55 U5.9@505,740.55 ; C61.1@830,650 855,675 U5.16@855,740.55 ; C61.1@836.5,655 v1(900,655) ; U12.4@1067.6,567.76 U12.5@1142.4,567.76 1197.76,567.76 C71.1@1210,580 ; v1(1210,525) C71.1@1210,580 ; C72.1@1325,585 1323.5,583.5 C71.1@1210,583.5 C71.1@1210,580 ; v1(1330,525) C72.1@1330,587.91 ; v1(1575,740) 1575.55,740.55 U6.9@1620,740.55 ; C62.1@1950,655 1970,675 U6.16@1970,740.55 ; C62.1@1951.5,655 v1(2015,655) ; U13.4@2182.6,567.76 2252.24,567.76 U13.5@2255,565 ; U13.5@2257.4,567.76 2302.76,567.76 C73.1@2320,585 ; v1(2320,525) C73.1@2320,583.5 C74.1@2440,583.5 ; v1(2440,525) C74.1@2440,583.5 ; C74.1@2440,587.91 C74.1@2440,583.5 ; v1(2695,740) 2695.87,740.87 U7.9@2740,740.87 ; C66.1@3070,655 3090,675 U7.16@3090,740.87 ; C66.1@3071.5,655 v1(3135,655) ; U14.4@3302.6,567.76 3372.76,567.76 U14.5@3375,570 ; U14.5@3377.4,567.76 3427.76,567.76 C75.1@3445,585 ; C75.1@3445,583.5 3563.5,583.5 C76.1@3565,585 ; C76.1@3560,587.91 3642.91,587.91 v1(3645,590) ; U15.4@3767.6,567.76 3837.76,567.76 U15.5@3840,570 ; U15.5@3842.4,567.76 3892.76,567.76 C77.1@3910,585 ; C77.1@3910,583.5 4028.5,583.5 C78.1@4030,585 ; C78.1@4030,587.91 4112.09,587.91 v1(4115,585) ; v1(4270,740) 4270.87,740.87 U8.9@4315,740.87 ; C67.1@4645,655 4665,675 U8.16@4665,740.87 ; C67.1@4646.5,655 4695,655 v1(4710,670) ; v1(5140,740) 5140.87,740.87 U9.9@5185,740.87 ; C63.1@5515,655 5535,675 U9.16@5535,740.87 ; C63.1@5516.5,655 v1(5580,655) ; v1(6010,740) 6010.87,740.87 U10.9@6055,740.87 ; C64.1@6385,655 6405,675 U10.16@6405,740.87 ; C64.1@6386.5,655 v1(6450,655) ; v1(6805,740) 6805.87,740.87 U11.9@6850,740.87 ; C65.1@7180,660 7200,680 U11.16@7200,740.87 ; C65.1@7181.5,655 v1(7245,655)
  Top Layer w25: C79.2@1505,661.61 1556.61,661.61 1575,680 v1(1575,740) ; v1(2225,150) C82.2@2353.39,150 ; v1(2535,250) C80.2@2663.39,250 ; C81.2@5221.61,250 v1(5325,250) ; C83.2@5526.61,150 v1(5526.61,228.39) ; C68.2@6660,721.61 6726.61,721.61 6745,740 v1(6805,740) ; U16.4@7502.6,567.76 U16.5@7577.4,567.76 7624.25,567.76 C69.1@7640,583.5 7644.41,587.91 C70.1@7765,587.91 v1(7765,530)
  Top Layer w30: C57.1@1355,855 1425,785 v1(1425,740) ; C58.1@2475,860 2535,800 v1(2535,740) ; C59.1@3550.31,812.01 3617.99,812.01 3645,785 v1(3645,740) ; C60.1@4100,855 4100,795 4120,775 v1(4120,740)
  MidLayer1 w25: v1@5525,230 v1(5526.61,228.39)
DOUTN_CH_U: J32.7 R38.2 | length 3016.9
  Top Layer w10: R38.2@535,593.5 535,530 755,310 3215,310 3235,290 3235,206.7 J32.7@3285.01,156.69
DOUTN_CH_V: J32.11 R41.2 | length 2156.3
  Top Layer w10: R41.2@1650,593.5 1650,510 1770,390 3405,390 3435,360 3435,205 J32.11@3485,155
DOUTN_CH_W: J32.15 R44.2 | length 1281.5
  Top Layer w10: R44.2@2780,593.5 2770,583.5 2770,495 2795,470 3580,470 3635,415 3635,205 J32.15@3685,155
DOUTN_U_PH: J32.20 R47.2 | length 766.3
  Top Layer w10: J32.20@3885,255 3885,505 3925,545 4330,545 4345,560 R47.2@4345,593.5
DOUTN_V_PH: J32.24 R50.2 | length 1376.4
  Top Layer w10: J32.24@4085,255 4085,405 4130,450 4457.01,450 4523.28,516.27 4523.28,516.57 4556.71,550 5200,550 5215,565 R50.2@5215,593.5 R50.2@5215,595
DOUTN_VDC: J32.32 R56.2 | length 2573.4
  Top Layer w10: J32.32@4485.01,256.69 4490.13,256.69 4623.28,389.84 ; 4623.28,390 4623.28,389.84 ; R56.2@6880,595 R56.2@6880,593.5 6880,530 6739.84,389.84 4623.28,389.84
DOUTN_W_PH: J32.28 R53.2 | length 2042.5
  Top Layer w10: J32.28@4285,255 4285,350 4305,370 4490.15,370 4590.15,470 5485,470 6035,470 6090,525 R53.2@6090,593.5 ; R53.2@6095,593.5 R53.2@6095,595
DOUTP_CH_U: J32.8 R39.2 | length 2905.3
  Top Layer w10: R39.2@605,593.5 605,510 635,480 ; 635.09,480.09 637.2,477.97 637.2,477.63 665.43,449.4 665.6,449.4 ; 665,450 665.6,449.4 ; J32.8@3285,255 3285,315 3270,330 785,330 665.6,449.4
DOUTP_CH_V: J32.12 R42.2 | length 2031.5
  Top Layer w10: R42.2@1720,593.5 1720,490 1800,410 3445,410 3485.01,369.99 J32.12@3485.01,256.69
DOUTP_CH_W: J32.16 R46.2 | length 1151.3
  Top Layer w10: R46.2@2840,593.5 2840,525 2875,490 3665,490 3685,470 J32.16@3685,255
DOUTP_U_PH: J32.19 R48.2 | length 893.6
  Top Layer w10: J32.19@3885.01,156.69 3935,206.68 3935,475 3985,525 4390,525 4415,550 R48.2@4415,593.5
DOUTP_V_PH: J32.23 R51.2 | length 1510.4
  Top Layer w10: J32.23@4085,155 4135,205 4135,395 4170,430 4465.29,430 4543.28,507.98 4543.28,508.28 4564.99,530 5251.02,530 5285,563.98 R51.2@5285,593.5
DOUTP_VDC: J32.31 R58.2 | length 2718.6
  Top Layer w10: J32.31@4485.01,156.69 4535,206.68 4535,273.28 4631.57,369.84 6789.84,369.84 6950,530 R58.2@6950,590
DOUTP_W_PH: J32.27 R55.2 | length 2155.3
  Top Layer w10: J32.27@4285,155 4335,205 4335,305 4380,350 4498.43,350 4598.43,450 6085,450 6160,525 R55.2@6160,593.5
GND_PH: C1.1 C2.2 C9.1 C20.2 C21.2 C22.1 C23.2 C24.1 C25.2 C26.1 C27.1 C28.1 C29.1 C30.1 C31.1 C35.1 C36.2 C37.1 C38.1 C39.2 C40.1 C41.1 C42.2 C43.1 C44.1 C49.1 C50.2 C52.2 C54.2 C60.2 C87.2 C95.1 C111.1 C112.2 C125.1 C134.2 C144.2 C147.1 C148.1 C149.1 D1.2 D2.1 D6.1 D11.3 D12.3 D13.3 D18.2 FB19.1 FB21.1 FB23.1 J16.2 J17.2 R8.2 R11.2 R14.1 R19.2 T4.4 U1.3 U1.4 U1.9 U8.8 U9.8 U10.8 U18.1 | length 3490.5
  Top Layer w10: C27.1@4021.5,1540 v1(4065,1540)
  Top Layer w15: U1.9@3931.8,1702.4 U1.3@3931.8,1767
  Top Layer w20: D1.2@3865,2387.52 3870.04,2387.52 D2.1@3935,2452.48 3977.52,2452.48 3990,2440 v1(3990,2400) ; U1.9@3931.8,1702.4 U1.9@3944.2,1690 ; C147.1@4252.91,1290 4240,1277.09 v1(4240,1190) C50.2@4288.5,1190 4288.5,1156.5 4315,1130 U8.8@4315,1099.13 ; C36.2@4275,1576.5 4296.5,1555 v1(4320,1555) C29.1@4373.5,1555 ; v1(4320,1620) C21.2@4373.5,1620 ; v1(4345,2015) 4394.53,1965.47 4454.53,1965.47 R8.2@4460,1960 ; v1(4400,1375) 4415,1375 C37.1@4465,1325 4491.5,1351.5 D11.3@4491.5,1455 4533.5,1455 FB19.1@4548.03,1469.53 ; FB19.1@4550,1469.53 FB19.1@4548.03,1469.53 ; FB19.1@4550,1471.5 FB19.1@4548.03,1469.53 ; C38.1@4720,1325 v1(4775,1380) ; C22.1@4815,1751.5 v1(4815,1800) ; C39.2@5110,1586.5 5146.5,1586.5 v1(5170,1610) C23.2@5223.5,1610 ; C148.1@5137.91,1295 5137.91,1262.91 5110,1235 v1(5110,1190) C52.2@5158.5,1190 5158.5,1161.5 5185,1135 U9.8@5185,1099.13 ; v1(5170,1545) C30.1@5223.5,1545 ; v1(5195,2005) 5230,1970 5265,1970 R11.2@5275,1960 ; D12.3@5351.5,1440 5351.5,1466.5 ; C40.1@5355,1320 v1(5355,1385) ; 5360.2,1475.2 5351.5,1466.5 ; FB21.1@5435,1461.5 FB21.1@5431.97,1464.53 ; FB21.1@5435,1464.53 FB21.1@5431.97,1464.53 ; C41.1@5600,1320 v1(5600,1395) ; C24.1@5665,1741.5 v1(5665,1790) ; C42.2@5985,1586.5 6021.5,1586.5 v1(6045,1610) C25.2@6098.5,1610 ; C149.1@5992.91,1295 5980,1282.09 v1(5980,1190) C54.2@6027.52,1190 ; C54.2@6027.52,1190.99 C54.2@6027.52,1190 ; C54.2@6028.5,1190 C54.2@6027.52,1190 ; v1(6045,1545) C31.1@6098.5,1545 ; v1(6045,1950) 6055,1960 R19.2@6135,1960 ; U10.8@6055,1099.13 6054.01,1100.12 6054.01,1125.99 6027.52,1152.49 C54.2@6027.52,1190 ; C43.1@6220,1335 v1(6220,1405) 6220,1455 D13.3@6220.75,1455.75 ; D13.3@6221.5,1455 6246.02,1479.53 FB23.1@6305,1479.53 ; C44.1@6470,1335 v1(6470,1410) ; C26.1@6540,1741.5 v1(6540,1790) ; 5351.5,1466.5 v1(5380,1495) 5401.5,1495 FB21.1@5431.97,1464.53
  Top Layer w25: C49.1@3902.91,1250 3915,1237.91 T4.4@3915,1099.84
  Top Layer w30: T4.4@3915,1099.84 4055.16,1099.84 C60.2@4100,1055
  Bottom Layer w20: C112.2@3852.4,1662.76 C112.2@3853.9,1664.25 ; C112.2@3853.9,1667.76 C112.2@3853.9,1664.25 ; U18.1@3864.8,1735.51 3864.8,1675.16 C112.2@3853.9,1664.25
  other v1: 3850,1310 3885,1355 3835,1365 3670,1615 3710,1615 3925,1675 3965,1675 4010,1675 3925,1710 3965,1710 4010,1710 3840,2050 3865,2085
GND_USH: C57.2 C88.1 C89.2 C90.1 C96.2 C102.1 C107.1 C113.1 C114.2 C115.2 C116.1 C126.1 C127.2 C128.1 C138.2 C139.1 D4.2 D14.1 D19.1 D21.2 J1.1 J1.2 J18.2 J19.2 R64.1 T1.4 U19.3 U19.4 U19.9 U21.1 | length 999.4
  Top Layer w20: D14.1@397.48,1160 v1(435,1160.04) v1(435,1160.04) ; D4.2@1270,2232.52 1270,2190 v1(1280,2180)
  Top Layer w25: T1.4@1205,1099.84 1245.16,1099.84 ; T1.4@1205,1100 T1.4@1205,1120
  Top Layer w40: 1245.16,1099.84 1310.16,1099.84 C57.2@1355,1055
  Bottom Layer w20: D19.1@1215,2180.2 1279.8,2180.2 v1(1280,2180) 1290,2170 1290,1955 1273.5,1938.5 C89.2@1235,1938.5 ; C116.1@1226.5,1615 1226.5,1651.5 v1(1235,1660)
  Bottom Layer w25: 1010,1320 1002.09,1312.09 C138.2@1002.09,1220 C139.1@1107.91,1220 ; C139.1@1110,1220 C139.1@1107.91,1220 ; 1110,1320 1107.91,1317.91 C139.1@1107.91,1220
  other v1: 1065,1330 1035,1365 1080,1395 515,1495 570,1495 1040,1725 1080,1725 1135,1750 1195,1760 1250,1760 1270,1805 1270,1890
GND_USH1: C3.1 C4.2 C17.1 C32.2 C46.2 FB3.1 J2.1 J2.2 J9.2 U5.8 | length 781.3
  Top Layer w20: C17.1@452.09,1345 467.09,1330 v1(503,1330) C32.2@548.5,1330 548.5,1265 C46.2@545,1261.5 ; C17.1@457.09,1345 457.09,1367.09 C17.1@466.5,1376.5 ; v1(495,1170) 505,1160 U5.8@505,1098.82 ; C3.1@660,1945 660,1990 v1(685,2015) ; J9.2@675,2350 770,2255 770,2111.5 FB3.1@750,2091.5 ; FB3.1@745,2086.5 FB3.1@750,2091.5 ; FB3.1@750,2084.53 FB3.1@750,2091.5 ; v1(870,2030) 870,2025 900,1995 C4.2@900,1945
GND_VDC: C101.2 C106.1 C123.1 C124.2 C135.2 C136.1 C145.2 D7.1 D24.2 J8.1 J8.2 J25.2 T5.5 U24.1 | length 819.6
  Top Layer w25: J25.2@7430,1420 7430,1280 7540,1170 ; T5.5@7540,1099.84 7540,1170 ; v1(7765,1190) 7560,1190 7540,1170 ; D7.1@7772.48,2025 v1(7810,2025)
  Bottom Layer w8: v1(7375,1525) 7377.91,1527.91 C123.1@7470,1527.91 ; C136.1@7742.09,1392.91 C136.1@7742.09,1425
  Bottom Layer w25: D24.2@7665.2,1945 v1(7720,1945)
  other v1: 7775,1245 7775,1290 7775,1330 7370,1395 7370,1465 7740,1525 7740,1595 7740,1665 7740,1730 7715,1795 7720,1905
GND_VSH: C58.2 C91.1 C92.1 C93.2 C98.2 C103.1 C108.1 C117.1 C118.2 C119.2 C120.1 C129.1 C130.1 C137.2 C140.2 C141.1 D5.2 D15.1 D20.1 D22.2 J3.1 J3.2 J20.2 J21.2 R65.1 T2.4 U20.3 U20.4 U20.9 U22.1 | length 1050
  Top Layer w8: J20.2@2120,1400 J20.2@2120,1425
  Top Layer w20: D15.1@1512.48,1160 v1(1553.74,1160) ; v1@2390,2195 D5.2@2390,2242.52
  Top Layer w25: T2.4@2320,1118.5 T2.4@2320,1099.84 2360.16,1099.84
  Top Layer w40: 2335,1115 2420,1115 C58.2@2475,1060
  Bottom Layer w20: D20.1@2330,2185 D20.1@2330,2180.2 2389.8,2180.2 v1(2390,2180) 2405,2165 2405,1955 2388.5,1938.5 C93.2@2350,1938.5 ; C120.1@2341.5,1615 2341.5,1651.5 v1(2350,1660)
  Bottom Layer w25: 2117.91,1332.09 2130,1320 ; 2127.5,1317.5 2132.09,1312.91 2132.09,1220 C141.1@2222.91,1220 2222.91,1317.91 2225,1320
  other v1: 2185,1310 2160,1360 2205,1360 1625,1495 1680,1495 2155,1725 2270,1755 2330,1755 2385,1755 1950,1795 2395,1815 2395,1875
GND_VSH1: C5.1 C6.2 C18.1 C33.2 C47.2 FB5.1 J4.1 J4.2 J10.2 U6.8 | length 718.5
  Top Layer w20: C18.1@1562.09,1345 1577.09,1330 v1(1615,1330) C33.2@1663.5,1330 1663.5,1265 C47.2@1660,1261.5 ; v1(1599.29,1160.04) 1620,1139.33 U6.8@1620,1098.82 ; C5.1@1775,1955 v1(1775,2030) ; J10.2@1800,2345 1880,2265 1880,2121.5 FB5.1@1860,2101.5 ; v1(2005,2060) 2020,2045 C6.2@2020,1955
GND_WSH: C59.2 C84.1 C85.1 C86.2 C100.2 C104.1 C105.2 C109.1 C110.1 C121.1 C122.2 C131.1 C132.2 C133.1 C142.2 C143.1 D3.2 D16.1 D17.1 D23.2 J5.1 J5.2 J23.2 J24.2 R63.1 T3.4 U17.3 U17.4 U17.9 U23.1 | length 660.8
  Top Layer w20: D16.1@2627.48,1160 v1(2668.74,1160) ; D3.2@3465,2302.52 3512.48,2302.52 v1(3515,2300)
  Top Layer w25: v1(3270,1320) v1(3320,1320)
  Top Layer w40: 3445,1180 3445,1160.63 3482.81,1122.82 3482.81,1083.45 C59.2@3550.31,1015.94
  Bottom Layer w20: v1@3386.5,1661.5 C110.1@3386.5,1705 ; D17.1@3455,2295 D17.1@3465,2305 ; D17.1@3455,2310.2 3504.8,2310.2 v1(3515,2300)
  Bottom Layer w25: v1(3270,1320) 3270,1330 v1(3315,1375) ; v1(3320,1320) 3342.91,1297.09 C143.1@3342.91,1220 ; 3342.91,1320 3342.91,1322.91 3345,1325
  other v1: 2745,1495 2800,1495 3385,1660 3210,1850 3290,1850 3390,1850 3120,1870 3445,1870 3390,1910 3445,1910
GND_WSH1: C7.1 C8.2 C34.2 C48.2 C146.1 FB17.1 J6.1 J6.2 J11.2 U7.8 | length 725.8
  Top Layer w20: C146.1@2692.09,1375 2707.09,1360 v1(2745,1360) C34.2@2793.5,1360 2790,1356.5 C48.2@2790,1266.5 ; U7.8@2740,1099.13 v1@2740,1170 ; v1(2880,2030) 2895,2015 C7.1@2895,1945 ; J11.2@2920,2345 3005,2260 3005,2111.5 FB17.1@2985,2091.5 ; v1(3125,2005) 3135,1995 C8.2@3135,1945
  other v1: 2740,1172
GND_XSH1: C10.1 C11.2 C19.1 C45.2 C56.2 FB16.1 J7.1 J7.2 J15.2 U11.8 | length 1003.8
  Top Layer w20: v1(6775,1190) C56.2@6823.5,1190 6823.5,1165.51 6850,1139.01 U11.8@6850,1099.13 ; J15.2@7020,2350 7105,2265 7105,2111.5 7080,2086.5 FB16.1@7080,2084.53
  Top Layer w25: v1(6775,1190) 6775,1282.09 C19.1@6787.91,1295 ; C45.2@6871.5,1520 6906.5,1555 v1(6945,1555) ; v1(7000,1870) C10.1@7000,1945 7000,2049.53 7035,2084.53 FB16.1@7080,2084.53 ; v1(7245,1875) C11.2@7245,1945
NetC3_2: C3.2 C12.2 D25.3 FB3.2 U5.3 | length 1109.2
  Top Layer w20: FB3.2@745,2023.5 772.2,1996.3 772.2,1982.2 740,1950 C3.2@740,1945 765,1920 765,1886.5 C12.2@743.5,1865 762,1846.5 762,1172 v1(755,1165) U5.3@755,1098.82
  Bottom Layer w15: D25.3@676.5,1240 715,1240 755,1200 v1(755,1165)
NetC4_1: C4.1 C12.1 D28.3 FB2.2 U5.2 | length 1129.8
  Top Layer w20: U5.2@805,1098.82 v1(805,1170) 790,1185 790,1848.5 C12.1@806.5,1865 793,1878.5 793,1918 C4.1@820,1945 800.2,1964.8 800.2,2008.7 FB2.2@815,2023.5
  Bottom Layer w15: D28.3@681.5,1115 775,1115 805,1145 v1(805,1170)
NetC5_2: C5.2 C13.2 D31.3 FB5.2 U6.3 | length 1108.8
  Top Layer w20: FB5.2@1860,2038.5 1887.2,2011.3 1887.2,1996.8 1855,1964.6 C5.2@1855,1955 1889,1921 1889,1894 1868.5,1873.5 C13.2@1868.5,1870 1880,1858.5 1880,1185 v1(1870,1175) U6.3@1870,1098.82
  Bottom Layer w10: D31.3@1796.5,1115 D31.3@1806.5,1115 1835,1115 1865,1145 1870,1150 v1(1870,1175)
NetC6_1: C6.1 C13.1 D26.3 FB4.2 U6.2 | length 1157.4
  Top Layer w20: U6.2@1920,1098.82 v1(1920,1175) 1908,1187 1908,1846.5 C13.1@1931.5,1870 1917,1884.5 1917,1932 C6.1@1940,1955 1915.2,1979.8 1915.2,2018.7 FB4.2@1935,2038.5
  Bottom Layer w10: D26.3@1796.5,1240 D26.3@1801.5,1240 1886.73,1240 1920,1206.73 v1(1920,1175)
NetC7_2: C7.2 C14.2 D34.3 FB17.2 U7.3 | length 1087.8
  Top Layer w20: FB17.2@2985,2028.5 3005,2008.5 3005,1975 C7.2@2975,1945 3005,1915 3005,1876.5 C14.2@2988.5,1860 3005,1843.5 3005,1190 v1(2990,1175) U7.3@2990,1099.13
  Bottom Layer w20: D34.3@2911.5,1110 2976.5,1175 v1(2990,1175)
NetC8_1: C8.1 C14.1 D27.3 FB7.2 U7.2 | length 1133.8
  Top Layer w20: U7.2@3040,1099.13 v1(3040,1175) 3040,1183 3035,1188 3035,1843.5 C14.1@3051.5,1860 3033,1878.5 3033,1923 C8.1@3055,1945 3033,1967 3033,2011.5 FB7.2@3050,2028.5
  Bottom Layer w20: D27.3@2916.5,1220 3030,1220 3040,1210 v1(3040,1175)
NetC9_2: C9.2 C15.2 FB1.1 R15.2 U1.1 | length 362.5
  Top Layer w10: U1.1@3983,1767 3983,1803 4001.5,1821.5 C15.2@4001.5,1845 ; C15.2@4000,1845 4000,1913.5 R15.2@4001.5,1915 ; R15.2@4000,1915 4032.09,1947.09 C9.2@4032.09,2015 FB1.1@4032.09,2107.91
